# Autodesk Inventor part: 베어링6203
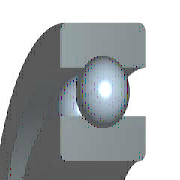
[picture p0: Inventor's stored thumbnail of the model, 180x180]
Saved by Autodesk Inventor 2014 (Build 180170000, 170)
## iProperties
IsCustomPart: 0
Company: 한국ATC센터
Created: 2014-12
Part Number: 베어링6203
Material: 강, 연강
Description: 깊은 그루브 볼 베어링
Document SubType Name: Modeling
Standard: KS B 2023
Designer: KYOUNG IL JANG
Standards Organization: KS
Language: ko-KR
Size Designation: 6203 - 17 x 40 x 12
Categories: <MemberInstance><Categories><Category DisplayName="샤프트 부품" InternalName="7f7aeb1f-a693-4053-b835-cee3144e0d98" Mnemonic="SHFT"><Category DisplayName="베어링" Inter
Density: 7.86 g/cm^3
Mass: 64.9809 g
Surface Area: 64.3582 cm^2
Volume: 8.26729 cm^3
Appearance: 크롬 - 광택 검은색
Author: KYOUNG IL JANG
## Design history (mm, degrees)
sketch "스케치" dims "d0" = 5.98 (= -0.26 x WD + 0.26 x BD)
  geometry: L1 (3.01, 14.25)-(8.99, 14.25); L2 (6, 14.25)-(6, 11.26); L3 (6, 14.25)-(6, 17.24); L4 (3.778, 12.249)-(0, 12.249); L5 (0, 8.5)-(12, 8.5); L6 (3.778, 16.251)-(0, 16.251); L7 (0, 20)-(12, 20); L8 (12, 8.5)-(12, 12.249); L9 (8.222, 12.249)-(12, 12.249); L10 (8.222, 16.251)-(12, 16.251); L11 (12, 20)-(12, 16.251); L12 (-1.4, 0)-(8.4, 0) reference; L13 (0, -0.3)-(0, 5.3) reference
  constraints: 22 end point, 4 point on line, 2 collinear, 2 perpendicular, 2 symmetric about line, 1 midpoint, 1 parallel, 14 other
  dimensions: "d9" = 17 diameter of L5 L12 (= WD); "d11" = 40 diameter of L7 L12 (= BD); "d12" = 12 distance between parallel lines of L8 L13 (= KB); "d13" = 24.498 diameter of L9 L12 (= 0.326 x BD + 0.674 x WD)
revolve "본체" stored, may be unused: angle "d6" = 90 deg
revolve "볼" stored, may be unused: angle "d7" = 90 deg
pattern_circular "IDS_ARRAYBALL[SIMPL:T]" dims angle "d3" = 360 deg
body "Solid1"
fillet "모깎기1" dims "d1" = 0.6 (= KRS)
other parameters: "WD" = 17 [user parameter; used in 5 equation terms], "BD" = 40 [user parameter; used in 5 equation terms], "KB" = 12 [user parameter; used in 1 equation term], "KRS" = 0.6 [user parameter; used in 1 equation term], "d4" = 0, "d5" = 0, "d8" = 0, "d14" = 0, "d15" = 0, "BBA" = 0 [user parameter], "BC0" = 4750000 [user parameter], "BC" = 9560000 [user parameter], "WR" = 8.5 (= 0.5 x WD) [user parameter]
